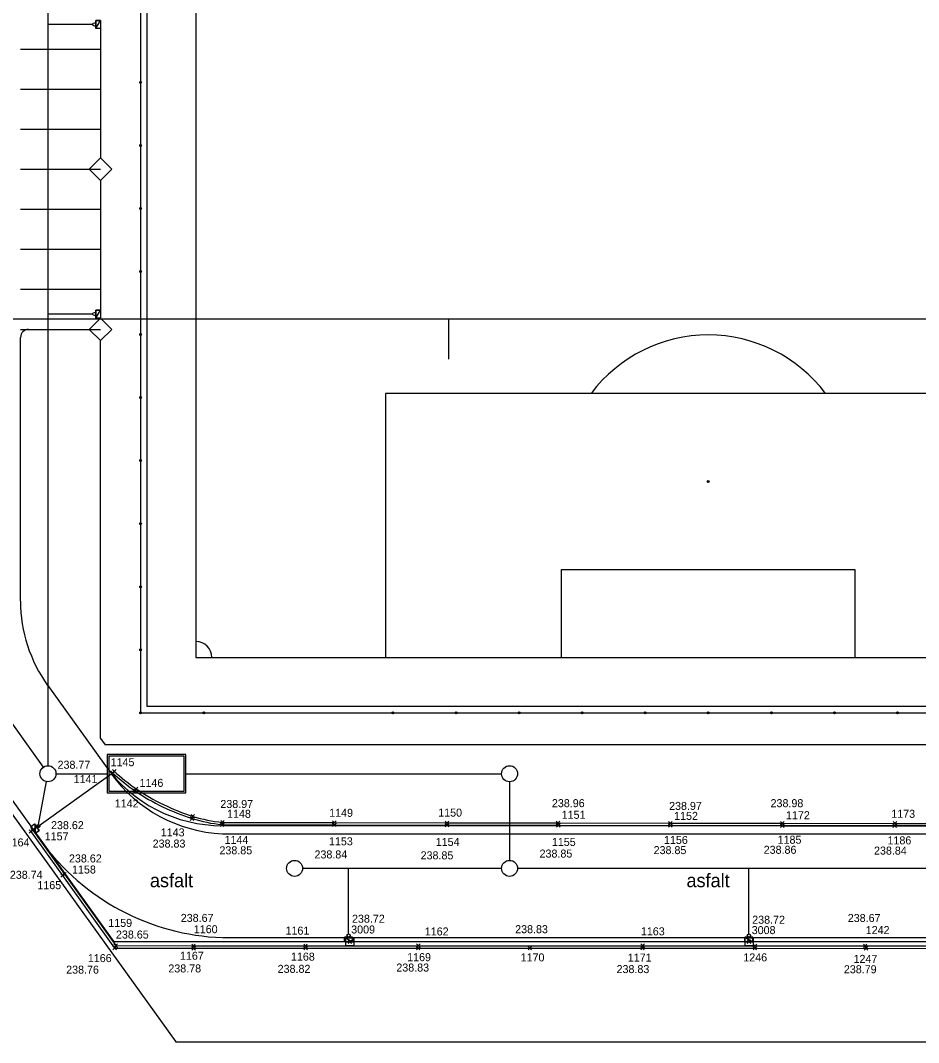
# Model space of a CAD drawing. Extents: x -264205 to -263615, y -1242401 to -1242031.
# Drawn here: x -264125.6 to -264069.5, y -1242315 to -1242251.2 of the extents above; entities that cross this region are included whole.
import ezdxf

# ---------------------------------------------------------------- set-up
doc = ezdxf.new("R2010")
doc.units = 0
for name, color, linetype in [('BODY_SYMBOL A CISLO_2-1', 7, 'Continuous'), ('BODY_VYSKA_2-1', 7, 'Continuous'), ('KOORDINACNA_SITUACIA_DSP', 7, 'Continuous'), ('POPIS', 7, 'Continuous'), ('PROJEKT_DRS_TDZ_VODOROVNE', 7, 'Continuous'), ('RAM_NA_TLAC_1-250_SITUACIA_2-1', 7, 'Continuous'), ('ROZHRANIE_SO_20-3_a_20-1', 7, 'Continuous'), ('SO_20-1_OBRUBNIKY_DOLNA_HRANA', 7, 'Continuous'), ('SO_20-1_OBRUBNIKY_HORNA_HRANA', 7, 'Continuous'), ('SO_20-1_UV', 7, 'Continuous')]:
    doc.layers.add(name, color=color, linetype=linetype)

msp = doc.modelspace()

# ---------------------------------------------------------------- linework, layer by layer
at = {"layer": 'BODY_SYMBOL A CISLO_2-1'}
for p, q in [((-264119.818, -1242298.204), (-264119.597, -1242297.982)), ((-264119.597, -1242298.204), (-264119.818, -1242297.982)), ((-264119.938, -1242298.291), (-264119.717, -1242298.069)), ((-264119.717, -1242298.291), (-264119.938, -1242298.069)), ((-264118.524, -1242299.427), (-264118.303, -1242299.205)), ((-264118.303, -1242299.427), (-264118.524, -1242299.205)), ((-264118.465, -1242299.289), (-264118.244, -1242299.069)), ((-264118.244, -1242299.289), (-264118.465, -1242299.069)), ((-264114.973, -1242301.149), (-264114.752, -1242300.927)), ((-264114.752, -1242301.149), (-264114.973, -1242300.927)), ((-264114.917, -1242301.009), (-264114.696, -1242300.789)), ((-264114.696, -1242301.009), (-264114.917, -1242300.789)), ((-264113.069, -1242301.387), (-264112.848, -1242301.167)), ((-264112.848, -1242301.387), (-264113.069, -1242301.167)), ((-264106.085, -1242301.397), (-264105.864, -1242301.177)), ((-264105.864, -1242301.397), (-264106.085, -1242301.177)), ((-264099.051, -1242301.411), (-264098.829, -1242301.191)), ((-264098.829, -1242301.411), (-264099.051, -1242301.191)), ((-264092.121, -1242301.424), (-264091.899, -1242301.204)), ((-264091.899, -1242301.424), (-264092.121, -1242301.204)), ((-264125.036, -1242301.957), (-264124.815, -1242301.735)), ((-264124.815, -1242301.957), (-264125.036, -1242301.735)), ((-264124.919, -1242301.873), (-264124.698, -1242301.651)), ((-264124.698, -1242301.873), (-264124.919, -1242301.651)), ((-264113.098, -1242301.529), (-264112.877, -1242301.308)), ((-264112.877, -1242301.529), (-264113.098, -1242301.308)), ((-264106.079, -1242301.543), (-264105.858, -1242301.323)), ((-264105.858, -1242301.543), (-264106.079, -1242301.323)), ((-264099.052, -1242301.556), (-264098.83, -1242301.336)), ((-264098.83, -1242301.556), (-264099.052, -1242301.336)), ((-264092.096, -1242301.57), (-264091.875, -1242301.35)), ((-264091.875, -1242301.57), (-264092.096, -1242301.35)), ((-264085.105, -1242301.438), (-264084.883, -1242301.217)), ((-264084.883, -1242301.438), (-264085.105, -1242301.217)), ((-264085.103, -1242301.579), (-264084.882, -1242301.357)), ((-264084.882, -1242301.579), (-264085.103, -1242301.357)), ((-264078.112, -1242301.593), (-264077.891, -1242301.372)), ((-264077.891, -1242301.593), (-264078.112, -1242301.372)), ((-264078.104, -1242301.445), (-264077.883, -1242301.225)), ((-264077.883, -1242301.445), (-264078.104, -1242301.225)), ((-264071.096, -1242301.6), (-264070.875, -1242301.379)), ((-264070.875, -1242301.6), (-264071.096, -1242301.379)), ((-264071.068, -1242301.45), (-264070.847, -1242301.228)), ((-264070.847, -1242301.45), (-264071.068, -1242301.228)), ((-264123.056, -1242304.703), (-264122.834, -1242304.481)), ((-264122.834, -1242304.703), (-264123.056, -1242304.481)), ((-264122.936, -1242304.63), (-264122.715, -1242304.409)), ((-264122.715, -1242304.63), (-264122.936, -1242304.409)), ((-264119.732, -1242309.083), (-264119.511, -1242308.863)), ((-264119.511, -1242309.083), (-264119.732, -1242308.863)), ((-264107.886, -1242309.095), (-264107.665, -1242308.873)), ((-264107.665, -1242309.095), (-264107.886, -1242308.873)), ((-264105.112, -1242308.847), (-264104.891, -1242308.627)), ((-264104.891, -1242308.847), (-264105.112, -1242308.627)), ((-264100.835, -1242309.093), (-264100.614, -1242308.872)), ((-264100.614, -1242309.093), (-264100.835, -1242308.872)), ((-264086.832, -1242309.093), (-264086.611, -1242308.872)), ((-264086.611, -1242309.093), (-264086.832, -1242308.872)), ((-264080.182, -1242308.839), (-264079.962, -1242308.617)), ((-264079.962, -1242308.839), (-264080.182, -1242308.617)), ((-264079.818, -1242309.096), (-264079.597, -1242308.874)), ((-264079.597, -1242309.096), (-264079.818, -1242308.874)), ((-264119.802, -1242309.235), (-264119.581, -1242309.015)), ((-264119.581, -1242309.235), (-264119.802, -1242309.015)), ((-264114.878, -1242309.102), (-264114.656, -1242308.88)), ((-264114.656, -1242309.102), (-264114.878, -1242308.88)), ((-264114.866, -1242309.249), (-264114.644, -1242309.029)), ((-264114.644, -1242309.249), (-264114.866, -1242309.029)), ((-264107.877, -1242309.242), (-264107.655, -1242309.022)), ((-264107.655, -1242309.242), (-264107.877, -1242309.022)), ((-264100.845, -1242309.245), (-264100.625, -1242309.024)), ((-264100.625, -1242309.245), (-264100.845, -1242309.024)), ((-264093.875, -1242309.244), (-264093.654, -1242309.022)), ((-264093.654, -1242309.244), (-264093.875, -1242309.022)), ((-264086.84, -1242309.237), (-264086.619, -1242309.015)), ((-264086.619, -1242309.237), (-264086.84, -1242309.015)), ((-264079.822, -1242309.242), (-264079.601, -1242309.021)), ((-264079.601, -1242309.242), (-264079.822, -1242309.021)), ((-264072.932, -1242309.099), (-264072.71, -1242308.877)), ((-264072.71, -1242309.099), (-264072.932, -1242308.877)), ((-264072.888, -1242309.258), (-264072.666, -1242309.038)), ((-264072.666, -1242309.258), (-264072.888, -1242309.038))]:
    msp.add_line(p, q, dxfattribs=at)
at = {"layer": 'KOORDINACNA_SITUACIA_DSP'}
for p, q in [((-264118.068, -1242187.532), (-264118.068, -1242294.432)), ((-264114.618, -1242190.982), (-264114.618, -1242290.982)), ((-264204.694, -1242191.482), (-264115.871, -1242314.982)), ((-264204.078, -1242191.482), (-264119.75, -1242308.732)), ((-264123.854, -1242237.976), (-264123.854, -1242297.736)), ((-264120.857, -1242251.689), (-264120.857, -1242251.189)), ((-264120.857, -1242251.189), (-264120.567, -1242251.189)), ((-264120.857, -1242251.689), (-264120.567, -1242251.189)), ((-264120.857, -1242251.689), (-264120.567, -1242251.189)), ((-264120.567, -1242251.189), (-264120.857, -1242251.189)), ((-264120.857, -1242251.189), (-264120.857, -1242251.689)), ((-264120.568, -1242251.191), (-264120.568, -1242259.775)), ((-264120.567, -1242251.189), (-264120.567, -1242251.689)), ((-264121.057, -1242251.439), (-264123.853, -1242251.439)), ((-264120.567, -1242251.689), (-264120.857, -1242251.689)), ((-264118.008, -1242255.057), (-264118.128, -1242255.057)), ((-264118.068, -1242255.117), (-264118.068, -1242254.997)), ((-264152.757, -1242258.05), (-264124.146, -1242297.83)), ((-264152.757, -1242258.05), (-264124.146, -1242297.83)), ((-264118.008, -1242258.995), (-264118.128, -1242258.995)), ((-264118.068, -1242259.055), (-264118.068, -1242258.935)), ((-264120.568, -1242261.189), (-264120.568, -1242269.774)), ((-264118.068, -1242262.992), (-264118.068, -1242262.872)), ((-264118.008, -1242262.932), (-264118.128, -1242262.932)), ((-264118.008, -1242266.87), (-264118.128, -1242266.87)), ((-264118.068, -1242266.93), (-264118.068, -1242266.81)), ((-264120.857, -1242269.775), (-264120.857, -1242269.275)), ((-264120.857, -1242269.275), (-264120.567, -1242269.275)), ((-264120.857, -1242269.775), (-264120.567, -1242269.275)), ((-264120.857, -1242269.775), (-264120.567, -1242269.275)), ((-264120.567, -1242269.275), (-264120.857, -1242269.275)), ((-264120.857, -1242269.275), (-264120.857, -1242269.775)), ((-264120.567, -1242269.275), (-264120.567, -1242269.775)), ((-264121.058, -1242269.525), (-264123.854, -1242269.525)), ((-264120.567, -1242269.775), (-264120.857, -1242269.775)), ((-264125.068, -1242270.482), (-264121.275, -1242270.482)), ((-264125.568, -1242287.467), (-264125.568, -1242270.982)), ((-264118.008, -1242270.807), (-264118.128, -1242270.807)), ((-264118.068, -1242270.867), (-264118.068, -1242270.747)), ((-264118.008, -1242274.745), (-264118.128, -1242274.745)), ((-264118.068, -1242274.805), (-264118.068, -1242274.685)), ((-264062.458, -1242274.482), (-264102.778, -1242274.482)), ((-264102.778, -1242274.482), (-264102.778, -1242290.982)), ((-264118.008, -1242278.682), (-264118.128, -1242278.682)), ((-264118.068, -1242278.742), (-264118.068, -1242278.622)), ((-264118.008, -1242282.62), (-264118.128, -1242282.62)), ((-264118.068, -1242282.68), (-264118.068, -1242282.56)), ((-264091.778, -1242290.982), (-264091.778, -1242285.482)), ((-264091.778, -1242285.482), (-264073.458, -1242285.482)), ((-264073.458, -1242285.482), (-264073.458, -1242290.982)), ((-264118.068, -1242286.617), (-264118.068, -1242286.497)), ((-264118.008, -1242286.557), (-264118.128, -1242286.557)), ((-264118.008, -1242290.495), (-264118.128, -1242290.495)), ((-264118.068, -1242290.555), (-264118.068, -1242290.435)), ((-264114.618, -1242290.982), (-264050.618, -1242290.982)), ((-264123.874, -1242292.722), (-264120.268, -1242297.737)), ((-264118.008, -1242294.432), (-264118.128, -1242294.432)), ((-264118.068, -1242294.492), (-264118.068, -1242294.372)), ((-264118.068, -1242294.432), (-264045.118, -1242294.432)), ((-264114.069, -1242294.432), (-264114.189, -1242294.432)), ((-264114.129, -1242294.492), (-264114.129, -1242294.372)), ((-264102.252, -1242294.432), (-264102.372, -1242294.432)), ((-264102.312, -1242294.492), (-264102.312, -1242294.372)), ((-264098.313, -1242294.432), (-264098.433, -1242294.432)), ((-264098.373, -1242294.492), (-264098.373, -1242294.372)), ((-264094.374, -1242294.432), (-264094.494, -1242294.432)), ((-264094.434, -1242294.492), (-264094.434, -1242294.372)), ((-264090.436, -1242294.432), (-264090.556, -1242294.432)), ((-264090.496, -1242294.492), (-264090.496, -1242294.372)), ((-264086.497, -1242294.432), (-264086.617, -1242294.432)), ((-264086.557, -1242294.492), (-264086.557, -1242294.372)), ((-264082.558, -1242294.432), (-264082.678, -1242294.432)), ((-264082.618, -1242294.492), (-264082.618, -1242294.372)), ((-264078.619, -1242294.432), (-264078.739, -1242294.432)), ((-264078.679, -1242294.492), (-264078.679, -1242294.372)), ((-264074.68, -1242294.432), (-264074.8, -1242294.432)), ((-264074.74, -1242294.492), (-264074.74, -1242294.372)), ((-264070.741, -1242294.432), (-264070.861, -1242294.432)), ((-264070.801, -1242294.492), (-264070.801, -1242294.372)), ((-264120.568, -1242296.035), (-264120.282, -1242296.432)), ((-264120.154, -1242297.036), (-264120.154, -1242299.436)), ((-264115.254, -1242297.036), (-264120.154, -1242297.036)), ((-264115.354, -1242297.136), (-264120.054, -1242297.136)), ((-264120.054, -1242297.136), (-264120.054, -1242299.336)), ((-264115.354, -1242299.336), (-264115.354, -1242297.136)), ((-264115.254, -1242299.436), (-264115.254, -1242297.036)), ((-264123.354, -1242298.236), (-264120.154, -1242298.236)), ((-264115.254, -1242298.236), (-264095.527, -1242298.236)), ((-264124.444, -1242301.414), (-264123.946, -1242298.728)), ((-264095.027, -1242298.736), (-264095.027, -1242303.647)), ((-264120.154, -1242299.436), (-264115.254, -1242299.436)), ((-264120.054, -1242299.336), (-264115.354, -1242299.336)), ((-264124.925, -1242301.537), (-264124.69, -1242301.368)), ((-264124.633, -1242301.943), (-264124.925, -1242301.537)), ((-264124.69, -1242301.368), (-264124.398, -1242301.774)), ((-264124.69, -1242301.368), (-264124.633, -1242301.943)), ((-264124.69, -1242301.368), (-264124.633, -1242301.943)), ((-264124.398, -1242301.774), (-264124.69, -1242301.368)), ((-264124.398, -1242301.774), (-264124.633, -1242301.943)), ((-264124.633, -1242301.943), (-264124.398, -1242301.774)), ((-263971.068, -1242301.482), (-264112.961, -1242301.482)), ((-264095.527, -1242304.147), (-264107.955, -1242304.147)), ((-264105.085, -1242308.242), (-264105.085, -1242304.147)), ((-264045.527, -1242304.147), (-264094.527, -1242304.147)), ((-264080.085, -1242308.242), (-264080.085, -1242304.147)), ((-264050.531, -1242308.732), (-264119.75, -1242308.732)), ((-264105.335, -1242308.442), (-264104.835, -1242308.442)), ((-264105.335, -1242308.732), (-264105.335, -1242308.442)), ((-264105.335, -1242308.442), (-264104.835, -1242308.732)), ((-264105.335, -1242308.442), (-264104.835, -1242308.732)), ((-264104.835, -1242308.442), (-264105.335, -1242308.442)), ((-264104.835, -1242308.732), (-264105.335, -1242308.732)), ((-264104.835, -1242308.442), (-264104.835, -1242308.732)), ((-264104.835, -1242308.732), (-264104.835, -1242308.442)), ((-264080.335, -1242308.442), (-264079.835, -1242308.442)), ((-264080.335, -1242308.732), (-264080.335, -1242308.442)), ((-264080.335, -1242308.442), (-264079.835, -1242308.732)), ((-264080.335, -1242308.442), (-264079.835, -1242308.732)), ((-264079.835, -1242308.442), (-264080.335, -1242308.442)), ((-264079.835, -1242308.732), (-264080.335, -1242308.732)), ((-264079.835, -1242308.442), (-264079.835, -1242308.732)), ((-264079.835, -1242308.732), (-264079.835, -1242308.442)), ((-264115.886, -1242314.982), (-264044.531, -1242314.982))]:
    msp.add_line(p, q, dxfattribs=at)
for points in [[(-264117.668, -1242187.932), (-264047.568, -1242187.932), (-264047.568, -1242294.032), (-264117.668, -1242294.032)], [(-264120.568, -1242259.775), (-264119.861, -1242260.482), (-264120.568, -1242261.189), (-264121.275, -1242260.482)], [(-264120.568, -1242269.775), (-264119.861, -1242270.482), (-264120.568, -1242271.189), (-264121.275, -1242270.482)]]:
    msp.add_lwpolyline(points, close=True, dxfattribs=at)
for points in [[(-264120.568, -1242296.035), (-264120.568, -1242271.189), (-264120.568, -1242271.189)], [(-263965.143, -1242296.432), (-264120.018, -1242296.432), (-264120.282, -1242296.432)]]:
    msp.add_lwpolyline(points, dxfattribs=at)
for centre, radius in [((-264120.957, -1242251.439), 0.1), ((-264118.068, -1242255.057), 0.06), ((-264118.068, -1242258.995), 0.06), ((-264118.068, -1242262.932), 0.06), ((-264118.068, -1242266.87), 0.06), ((-264120.958, -1242269.525), 0.1), ((-264118.068, -1242270.807), 0.06), ((-264118.068, -1242274.745), 0.06), ((-264118.068, -1242278.682), 0.06), ((-264082.618, -1242279.982), 0.06), ((-264118.068, -1242282.62), 0.06), ((-264118.068, -1242286.557), 0.06), ((-264118.068, -1242290.495), 0.06), ((-264118.068, -1242294.432), 0.06), ((-264114.129, -1242294.432), 0.06), ((-264102.312, -1242294.432), 0.06), ((-264098.373, -1242294.432), 0.06), ((-264094.434, -1242294.432), 0.06), ((-264090.496, -1242294.432), 0.06), ((-264086.557, -1242294.432), 0.06), ((-264082.618, -1242294.432), 0.06), ((-264078.679, -1242294.432), 0.06), ((-264074.74, -1242294.432), 0.06), ((-264070.801, -1242294.432), 0.06), ((-264123.854, -1242298.236), 0.5), ((-264095.027, -1242298.236), 0.5), ((-264124.462, -1242301.513), 0.1), ((-264108.455, -1242304.147), 0.5), ((-264095.027, -1242304.147), 0.5), ((-264105.085, -1242308.342), 0.1), ((-264080.085, -1242308.342), 0.1)]:
    msp.add_circle(centre, radius, dxfattribs=at)
for centre, radius, start, end in [((-264125.068, -1242270.982), 0.5, 90, 180), ((-264082.618, -1242279.982), 9.15, 36.94821, 143.05179), ((-264082.618, -1242279.982), 0.0303, 90, 270), ((-264082.618, -1242279.982), 0.0303, 270, 90), ((-264116.568, -1242287.467), 9, 180, 215.72401), ((-264114.618, -1242290.982), 1, 0, 90), ((-264112.961, -1242292.482), 9, 215.72401, 270)]:
    msp.add_arc(centre, radius, start, end, dxfattribs=at)
at = {"layer": 'PROJEKT_DRS_TDZ_VODOROVNE'}
for p, q in [((-264125.568, -1242252.982), (-264120.568, -1242252.982)), ((-264125.568, -1242255.482), (-264120.568, -1242255.482)), ((-264125.568, -1242257.982), (-264120.568, -1242257.982)), ((-264125.568, -1242260.482), (-264120.568, -1242260.482)), ((-264125.568, -1242262.982), (-264120.568, -1242262.982)), ((-264125.568, -1242265.482), (-264120.568, -1242265.482)), ((-264125.568, -1242267.982), (-264120.568, -1242267.982)), ((-264125.568, -1242270.482), (-264120.568, -1242270.482)), ((-264112.961, -1242301.982), (-263971.806, -1242301.982)), ((-264050.531, -1242308.482), (-264112.906, -1242308.482))]:
    msp.add_line(p, q, dxfattribs=at)
for centre, radius, start, end in [((-264112.56, -1242292.924), 9.068, 215.87399, 267.4682), ((-264112.435, -1242293.84), 14.642, 217.62012, 269.49568)]:
    msp.add_arc(centre, radius, start, end, dxfattribs=at)
at = {"layer": 'RAM_NA_TLAC_1-250_SITUACIA_2-1'}
msp.add_line((-264098.833, -1242269.835), (-264098.833, -1242272.335), dxfattribs=at)
msp.add_lwpolyline([(-264151.333, -1242269.835), (-263718.833, -1242269.835), (-263718.833, -1242344.085), (-264151.333, -1242344.085)], close=True, dxfattribs=at)
at = {"layer": 'ROZHRANIE_SO_20-3_a_20-1'}
msp.add_line((-264124.926, -1242301.846), (-264119.708, -1242298.093), dxfattribs=at)
at = {"layer": 'SO_20-1_OBRUBNIKY_DOLNA_HRANA'}
for points in [[(-264124.808, -1242301.762), (-264122.825, -1242304.519), (-264119.622, -1242308.973), (-264114.767, -1242308.991), (-264107.775, -1242308.984), (-264100.725, -1242308.982), (-264086.721, -1242308.982)], [(-264112.987, -1242301.418), (-264105.969, -1242301.433), (-264098.941, -1242301.446), (-264091.986, -1242301.46), (-264084.992, -1242301.468)], [(-264084.992, -1242301.468), (-264078.002, -1242301.482), (-264070.986, -1242301.489), (-264064.021, -1242301.482), (-264056.978, -1242301.482), (-264049.977, -1242301.481), (-264042.921, -1242301.475), (-264035.92, -1242301.469), (-264028.972, -1242301.456), (-264022.003, -1242301.442), (-264014.974, -1242301.438), (-264007.969, -1242301.429), (-264000.909, -1242301.426), (-263993.952, -1242301.425)], [(-264086.721, -1242308.982), (-264079.708, -1242308.985), (-264072.821, -1242308.988), (-264065.744, -1242308.997), (-264058.784, -1242309.009), (-264051.779, -1242308.995), (-264048.812, -1242308.996)]]:
    msp.add_lwpolyline(points, dxfattribs=at)
for centre, major_axis, ratio, start_param, end_param in [((-264108.973, -1242286.088), (13.129, -10.761), 0.957198, 4.669399, 4.776308), ((-264110.494, -1242287.503), (-7.141, -12.3), 0.999902, 6.218556, 6.497029), ((-264111.865, -1242291.044), (9.276, -4.796), 0.999118, 4.898081, 5.081552)]:
    msp.add_ellipse(centre, major_axis=major_axis, ratio=ratio, start_param=start_param, end_param=end_param, dxfattribs=at)
at = {"layer": 'SO_20-1_OBRUBNIKY_HORNA_HRANA'}
for points in [[(-264124.926, -1242301.846), (-264122.945, -1242304.592), (-264119.692, -1242309.125), (-264114.755, -1242309.139), (-264107.766, -1242309.132), (-264100.735, -1242309.134), (-264093.764, -1242309.133), (-264086.73, -1242309.126)], [(-264112.959, -1242301.277), (-264105.975, -1242301.287), (-264098.94, -1242301.301), (-264092.01, -1242301.314), (-264084.994, -1242301.327)], [(-264084.994, -1242301.327), (-264077.993, -1242301.335), (-264070.958, -1242301.339), (-264063.998, -1242301.345), (-264056.974, -1242301.334), (-264049.976, -1242301.332), (-264042.963, -1242301.324), (-264035.917, -1242301.32), (-264028.967, -1242301.31), (-264022.019, -1242301.3), (-264014.954, -1242301.285), (-264007.975, -1242301.28), (-264000.942, -1242301.277), (-263993.949, -1242301.276)], [(-264086.73, -1242309.126), (-264079.711, -1242309.131), (-264072.777, -1242309.148), (-264065.719, -1242309.143), (-264058.778, -1242309.157), (-264051.772, -1242309.139), (-264048.834, -1242309.14)]]:
    msp.add_lwpolyline(points, dxfattribs=at)
for centre, major_axis, ratio, start_param, end_param in [((-264109.865, -1242287.203), (11.619, -9.556), 0.975712, 4.666867, 4.782223), ((-264110.586, -1242287.673), (-7.289, -11.816), 0.999902, 6.242047, 6.527042), ((-264111.762, -1242290.774), (10.595, -0.535), 0.996454, 4.471564, 4.649627)]:
    msp.add_ellipse(centre, major_axis=major_axis, ratio=ratio, start_param=start_param, end_param=end_param, dxfattribs=at)
at = {"layer": 'SO_20-1_UV'}
for p, q in [((-264105.002, -1242308.737), (-264105.002, -1242308.737)), ((-264080.072, -1242308.728), (-264080.072, -1242308.728))]:
    msp.add_line(p, q, dxfattribs=at)
for points in [[(-264105.252, -1242308.737), (-264105.252, -1242308.487), (-264104.752, -1242308.487), (-264104.752, -1242308.987), (-264105.252, -1242308.987), (-264105.252, -1242308.737), (-264104.752, -1242308.737)], [(-264080.322, -1242308.728), (-264080.322, -1242308.478), (-264079.822, -1242308.478), (-264079.822, -1242308.978), (-264080.322, -1242308.978), (-264080.322, -1242308.728), (-264079.822, -1242308.728)]]:
    msp.add_lwpolyline(points, dxfattribs=at)

# ---------------------------------------------------------------- texts
at = {"layer": 'BODY_SYMBOL A CISLO_2-1'}
for s, p in [('1145', (-264119.944, -1242297.767)), ('1141', (-264122.254, -1242298.826)), ('1146', (-264118.138, -1242299.059)), ('1142', (-264119.683, -1242300.345)), ('1148', (-264112.671, -1242300.991)), ('1149', (-264106.294, -1242300.93)), ('1150', (-264099.485, -1242300.916)), ('1151', (-264091.774, -1242301.053)), ('1172', (-264077.767, -1242301.078)), ('1173', (-264071.194, -1242300.991)), ('1152', (-264084.753, -1242301.12)), ('1143', (-264116.812, -1242302.15)), ('1164', (-264126.499, -1242302.777)), ('1157', (-264124.058, -1242302.396)), ('1144', (-264112.828, -1242302.619)), ('1153', (-264106.308, -1242302.711)), ('1154', (-264099.64, -1242302.747)), ('1155', (-264092.387, -1242302.749)), ('1156', (-264085.386, -1242302.624)), ('1185', (-264078.29, -1242302.61)), ('1186', (-264071.428, -1242302.65)), ('1158', (-264122.352, -1242304.471)), ('1165', (-264124.518, -1242305.448)), ('1159', (-264120.089, -1242307.803)), ('1160', (-264114.749, -1242308.199)), ('1161', (-264109.019, -1242308.288)), ('3009', (-264104.92, -1242308.216)), ('1162', (-264100.324, -1242308.341)), ('1163', (-264086.829, -1242308.332)), ('3008', (-264079.908, -1242308.255)), ('1242', (-264072.79, -1242308.252)), ('1166', (-264121.365, -1242310.004)), ('1167', (-264115.613, -1242309.856)), ('1168', (-264108.681, -1242309.912)), ('1169', (-264101.424, -1242309.945)), ('1170', (-264094.34, -1242309.961)), ('1171', (-264087.647, -1242309.97)), ('1246', (-264080.433, -1242309.959)), ('1247', (-264073.548, -1242310.052))]:
    msp.add_text(s, height=0.5, dxfattribs=at).set_placement(p)
at = {"layer": 'BODY_VYSKA_2-1'}
for s, p in [('238.77', (-264123.256, -1242297.926)), ('238.97', (-264113.091, -1242300.378)), ('238.96', (-264092.385, -1242300.327)), ('238.98', (-264078.73, -1242300.327)), ('238.97', (-264085.067, -1242300.499)), ('238.62', (-264123.664, -1242301.7)), ('238.83', (-264117.318, -1242302.85)), ('238.85', (-264113.147, -1242303.271)), ('238.84', (-264107.212, -1242303.529)), ('238.85', (-264100.584, -1242303.586)), ('238.85', (-264093.156, -1242303.475)), ('238.85', (-264086.033, -1242303.26)), ('238.86', (-264079.16, -1242303.238)), ('238.84', (-264072.271, -1242303.288)), ('238.62', (-264122.544, -1242303.779)), ('238.74', (-264126.236, -1242304.8)), ('238.67', (-264115.563, -1242307.493)), ('238.72', (-264104.868, -1242307.544)), ('238.72', (-264079.877, -1242307.607)), ('238.67', (-264073.909, -1242307.497)), ('238.65', (-264119.61, -1242308.531)), ('238.83', (-264094.68, -1242308.197)), ('238.78', (-264116.338, -1242310.649)), ('238.83', (-264102.1, -1242310.593)), ('238.76', (-264122.72, -1242310.724)), ('238.82', (-264109.512, -1242310.674)), ('238.83', (-264088.347, -1242310.69)), ('238.79', (-264074.153, -1242310.7))]:
    msp.add_text(s, height=0.5, dxfattribs=at).set_placement(p)
at = {"layer": 'POPIS'}
for p in [(-264117.489, -1242305.325), (-264083.982, -1242305.325)]:
    msp.add_text('asfalt', height=0.8438, dxfattribs=at).set_placement(p)

doc.saveas('drawing.dxf')
